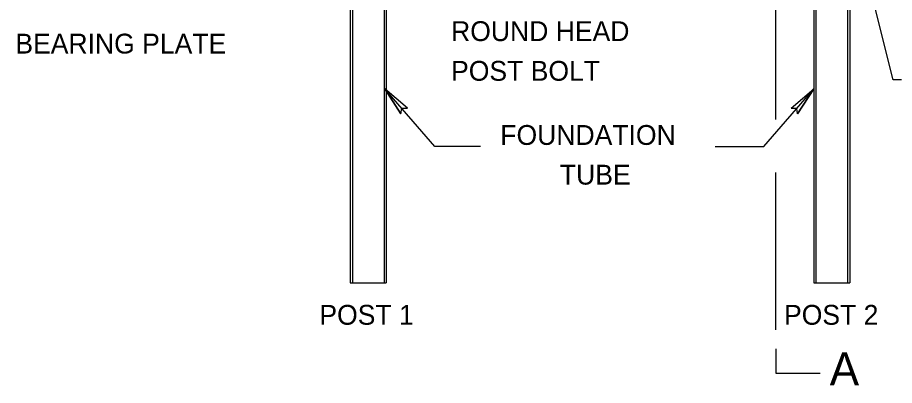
# Model space of a CAD drawing. Extents: x 12.2 to 54.5, y -7.8 to 16.1.
# Drawn here: x 12.638 to 15.289, y 13.015 to 14.128 of the extents above; entities that cross this region are included whole.
import ezdxf

# ---------------------------------------------------------------- set-up
doc = ezdxf.new("R2010")
doc.units = 0
for name, color, linetype in [('BORD-LINE', 7, 'Continuous'), ('DETL-DIMS', 7, 'Continuous'), ('DETL-NOTE', 7, 'Continuous'), ('DETL-TITL', 7, 'Continuous')]:
    doc.layers.add(name, color=color, linetype=linetype)

msp = doc.modelspace()

# ---------------------------------------------------------------- linework, layer by layer
at = {"layer": 'BORD-LINE'}
for p, q in [((13.6438, 14.6743), (13.6438, 13.3257)), ((13.6504, 14.6743), (13.6504, 13.3257)), ((13.7461, 14.6743), (13.7461, 13.3257)), ((13.7527, 14.6743), (13.7527, 13.3257)), ((15.0451, 14.6743), (15.0451, 13.3257)), ((15.0517, 14.6743), (15.0517, 13.3257)), ((15.1474, 14.6743), (15.1474, 13.3257)), ((15.154, 14.6743), (15.154, 13.3257)), ((13.6438, 13.3257), (13.7527, 13.3257)), ((15.0451, 13.3257), (15.154, 13.3257))]:
    msp.add_line(p, q, dxfattribs=at)
at = {"layer": 'DETL-DIMS'}
for p, q in [((14.931, 13.8194), (14.931, 14.5877)), ((15.2859, 13.9398), (15.1826, 14.349)), ((15.3109, 13.9398), (15.2859, 13.9398)), ((13.8997, 13.7376), (13.7486, 13.9128)), ((13.7971, 13.8363), (13.7486, 13.9128)), ((13.8169, 13.8534), (13.7486, 13.9128)), ((14.8941, 13.7376), (15.0451, 13.9128)), ((14.9769, 13.8534), (15.0451, 13.9128)), ((14.9966, 13.8363), (15.0451, 13.9128)), ((13.7971, 13.8363), (13.7999, 13.8533)), ((13.8169, 13.8534), (13.7999, 13.8533)), ((14.9769, 13.8534), (14.9939, 13.8533)), ((14.9966, 13.8363), (14.9939, 13.8533)), ((14.0376, 13.7376), (13.8997, 13.7376)), ((14.7473, 13.7376), (14.8941, 13.7376)), ((14.931, 13.1832), (14.931, 13.6593)), ((14.9316, 13.0515), (14.9316, 13.1264)), ((15.065, 13.0515), (14.9316, 13.0515))]:
    msp.add_line(p, q, dxfattribs=at)
for points in [[(13.8169, 13.8534), (13.7486, 13.9128), (13.7971, 13.8363), (13.7999, 13.8533)], [(14.9769, 13.8534), (15.0451, 13.9128), (14.9966, 13.8363), (14.9939, 13.8533)]]:
    msp.add_lwpolyline(points, close=True, dxfattribs=at)

# ---------------------------------------------------------------- texts
at = {"layer": 'DETL-NOTE'}
for s, p in [('ROUND HEAD', (13.9487, 14.0567)), ('BEARING PLATE', (12.6313, 14.019)), ('POST BOLT', (13.9487, 13.9367)), ('FOUNDATION', (14.0976, 13.7428)), ('TUBE', (14.2777, 13.6228)), ('POST 1', (13.5505, 13.199)), ('POST 2', (14.9554, 13.199))]:
    msp.add_text(s, height=0.06, dxfattribs=at).set_placement(p)
at = {"layer": 'DETL-TITL'}
msp.add_text('A', height=0.1, dxfattribs=at).set_placement((15.0934, 13.0154))

doc.saveas('drawing.dxf')
